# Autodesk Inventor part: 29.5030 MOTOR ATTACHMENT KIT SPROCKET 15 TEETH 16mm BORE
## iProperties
Created: 2006-12
Part Number: 29.5030 MOTOR ATTACHMENT KIT SPROCKET 15 TEETH 16mm BORE
Document SubType Name: Modeling
Designer: Andy Moles
Material: Steel
Density: 7.85 g/cm^3
Author: Andy Moles
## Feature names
1. Extrusion1
2. Extrusion2
3. Extrusion3
4. Circular Pattern1
5. Extrusion4
